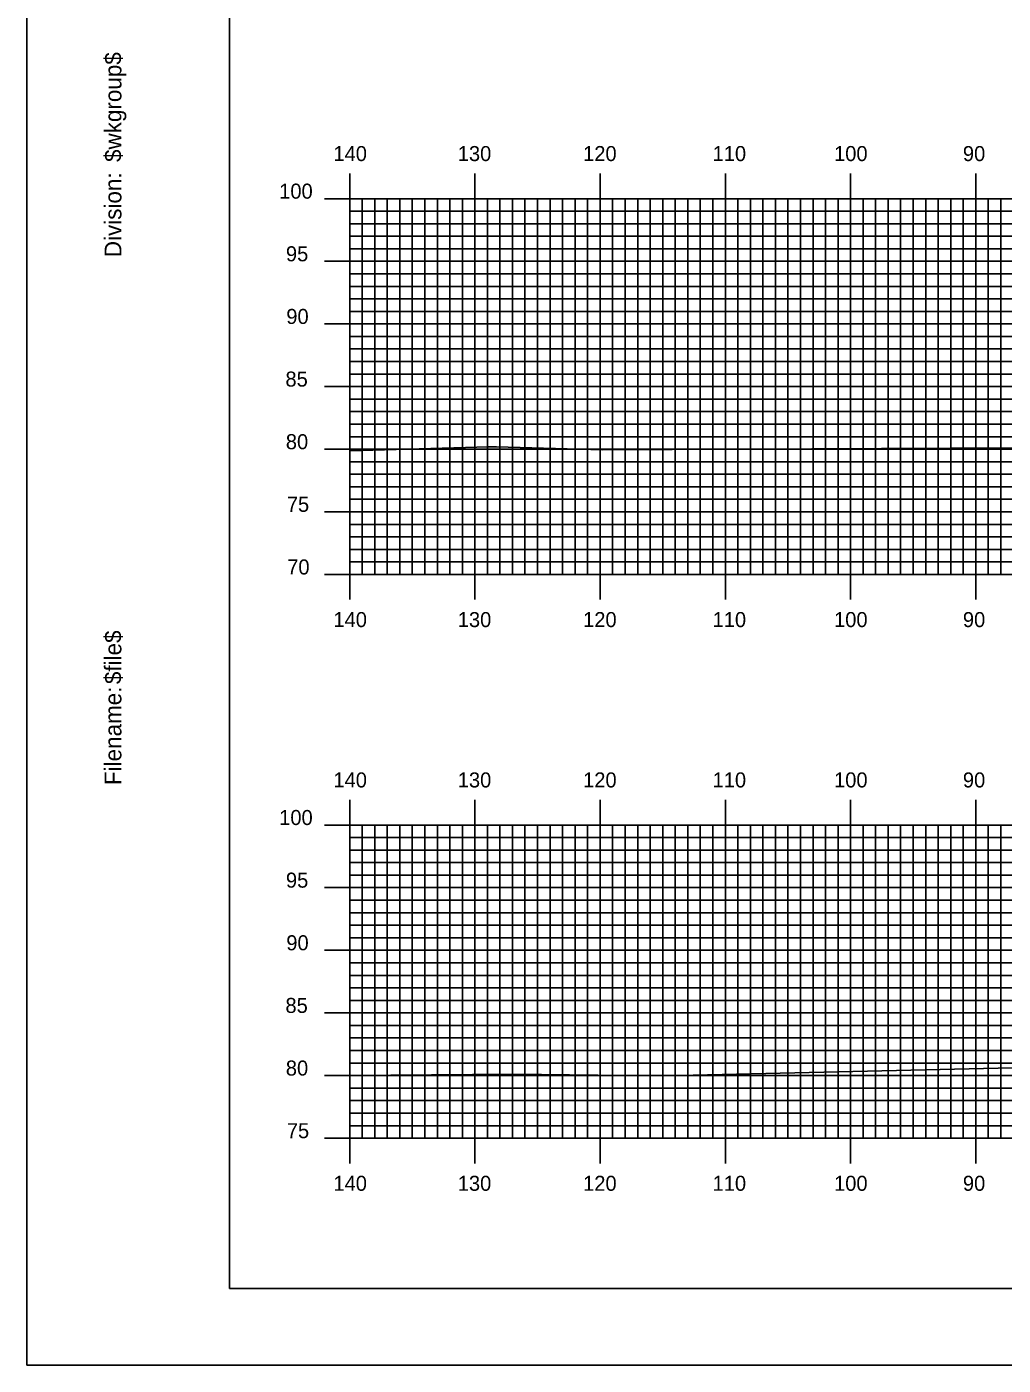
# Model space of a CAD drawing. Extents: x 1757462 to 1757806, y 442591 to 442811.
# Drawn here: x 1757462.3 to 1757540.3, y 442590.5 to 442697.4 of the extents above; entities that cross this region are included whole.
import ezdxf

# ---------------------------------------------------------------- set-up
doc = ezdxf.new("R2010")
doc.units = 0
for name, color, linetype in [('BORDER', 7, 'Continuous'), ('H_V ANNOTATION', 7, 'Continuous'), ('MAJOR', 7, 'Continuous'), ('MINOR', 7, 'Continuous'), ('PLOT BOUNDARY', 7, 'Continuous'), ('S_Roadway_Centerline', 7, 'Continuous')]:
    doc.layers.add(name, color=color, linetype=linetype)

msp = doc.modelspace()

# ---------------------------------------------------------------- linework, layer by layer
at = {"layer": 'BORDER'}
msp.add_lwpolyline([(1757478.51, 442596.67), (1757798.51, 442596.67), (1757798.51, 442806.67), (1757478.51, 442806.67)], close=True, dxfattribs=at)
at = {"layer": 'MAJOR'}
for p, q in [((1757488.11, 442685.67), (1757488.11, 442683.67)), ((1757498.11, 442685.67), (1757498.11, 442683.67)), ((1757508.11, 442685.67), (1757508.11, 442683.67)), ((1757518.11, 442685.67), (1757518.11, 442683.67)), ((1757528.11, 442685.67), (1757528.11, 442683.67)), ((1757538.11, 442685.67), (1757538.11, 442683.67)), ((1757486.11, 442683.67), (1757488.11, 442683.67)), ((1757488.11, 442683.67), (1757768.11, 442683.67)), ((1757488.11, 442653.67), (1757488.11, 442683.67)), ((1757488.11, 442653.67), (1757488.11, 442683.67)), ((1757488.11, 442683.67), (1757768.11, 442683.67)), ((1757498.11, 442653.67), (1757498.11, 442683.67)), ((1757508.11, 442653.67), (1757508.11, 442683.67)), ((1757518.11, 442653.67), (1757518.11, 442683.67)), ((1757528.11, 442653.67), (1757528.11, 442683.67)), ((1757538.11, 442653.67), (1757538.11, 442683.67)), ((1757486.11, 442678.67), (1757488.11, 442678.67)), ((1757488.11, 442678.67), (1757768.11, 442678.67)), ((1757486.11, 442673.67), (1757488.11, 442673.67)), ((1757488.11, 442673.67), (1757768.11, 442673.67)), ((1757486.11, 442668.67), (1757488.11, 442668.67)), ((1757488.11, 442668.67), (1757768.11, 442668.67)), ((1757486.11, 442663.67), (1757488.11, 442663.67)), ((1757488.11, 442663.67), (1757768.11, 442663.67)), ((1757486.11, 442658.67), (1757488.11, 442658.67)), ((1757488.11, 442658.67), (1757768.11, 442658.67)), ((1757486.11, 442653.67), (1757488.11, 442653.67)), ((1757488.11, 442653.67), (1757768.11, 442653.67)), ((1757488.11, 442653.67), (1757768.11, 442653.67)), ((1757488.11, 442651.66), (1757488.11, 442653.67)), ((1757498.11, 442651.66), (1757498.11, 442653.67)), ((1757508.11, 442651.66), (1757508.11, 442653.67)), ((1757518.11, 442651.66), (1757518.11, 442653.67)), ((1757528.11, 442651.66), (1757528.11, 442653.67)), ((1757538.11, 442651.66), (1757538.11, 442653.67)), ((1757488.11, 442635.67), (1757488.11, 442633.67)), ((1757498.11, 442635.67), (1757498.11, 442633.67)), ((1757508.11, 442635.67), (1757508.11, 442633.67)), ((1757518.11, 442635.67), (1757518.11, 442633.67)), ((1757528.11, 442635.67), (1757528.11, 442633.67)), ((1757538.11, 442635.67), (1757538.11, 442633.67)), ((1757486.11, 442633.67), (1757488.11, 442633.67)), ((1757488.11, 442633.67), (1757768.11, 442633.67)), ((1757488.11, 442608.67), (1757488.11, 442633.67)), ((1757488.11, 442608.67), (1757488.11, 442633.67)), ((1757488.11, 442633.67), (1757768.11, 442633.67)), ((1757498.11, 442608.67), (1757498.11, 442633.67)), ((1757508.11, 442608.67), (1757508.11, 442633.67)), ((1757518.11, 442608.67), (1757518.11, 442633.67)), ((1757528.11, 442608.67), (1757528.11, 442633.67)), ((1757538.11, 442608.67), (1757538.11, 442633.67)), ((1757486.11, 442628.67), (1757488.11, 442628.67)), ((1757488.11, 442628.67), (1757768.11, 442628.67)), ((1757486.11, 442623.67), (1757488.11, 442623.67)), ((1757488.11, 442623.67), (1757768.11, 442623.67)), ((1757486.11, 442618.67), (1757488.11, 442618.67)), ((1757488.11, 442618.67), (1757768.11, 442618.67)), ((1757486.11, 442613.67), (1757488.11, 442613.67)), ((1757488.11, 442613.67), (1757768.11, 442613.67)), ((1757486.11, 442608.67), (1757488.11, 442608.67)), ((1757488.11, 442608.67), (1757768.11, 442608.67)), ((1757488.11, 442608.67), (1757768.11, 442608.67)), ((1757488.11, 442606.66), (1757488.11, 442608.67)), ((1757498.11, 442606.66), (1757498.11, 442608.67)), ((1757508.11, 442606.66), (1757508.11, 442608.67)), ((1757518.11, 442606.66), (1757518.11, 442608.67)), ((1757528.11, 442606.66), (1757528.11, 442608.67)), ((1757538.11, 442606.66), (1757538.11, 442608.67))]:
    msp.add_line(p, q, dxfattribs=at)
at = {"layer": 'MINOR'}
for p, q in [((1757489.11, 442653.67), (1757489.11, 442683.67)), ((1757490.11, 442653.67), (1757490.11, 442683.67)), ((1757491.11, 442653.67), (1757491.11, 442683.67)), ((1757492.11, 442653.67), (1757492.11, 442683.67)), ((1757493.11, 442653.67), (1757493.11, 442683.67)), ((1757494.11, 442653.67), (1757494.11, 442683.67)), ((1757495.11, 442653.67), (1757495.11, 442683.67)), ((1757496.11, 442653.67), (1757496.11, 442683.67)), ((1757497.11, 442653.67), (1757497.11, 442683.67)), ((1757499.11, 442653.67), (1757499.11, 442683.67)), ((1757500.11, 442653.67), (1757500.11, 442683.67)), ((1757501.11, 442653.67), (1757501.11, 442683.67)), ((1757502.11, 442653.67), (1757502.11, 442683.67)), ((1757503.11, 442653.67), (1757503.11, 442683.67)), ((1757504.11, 442653.67), (1757504.11, 442683.67)), ((1757505.11, 442653.67), (1757505.11, 442683.67)), ((1757506.11, 442653.67), (1757506.11, 442683.67)), ((1757507.11, 442653.67), (1757507.11, 442683.67)), ((1757509.11, 442653.67), (1757509.11, 442683.67)), ((1757510.11, 442653.67), (1757510.11, 442683.67)), ((1757511.11, 442653.67), (1757511.11, 442683.67)), ((1757512.11, 442653.67), (1757512.11, 442683.67)), ((1757513.11, 442653.67), (1757513.11, 442683.67)), ((1757514.11, 442653.67), (1757514.11, 442683.67)), ((1757515.11, 442653.67), (1757515.11, 442683.67)), ((1757516.11, 442653.67), (1757516.11, 442683.67)), ((1757517.11, 442653.67), (1757517.11, 442683.67)), ((1757519.11, 442653.67), (1757519.11, 442683.67)), ((1757520.11, 442653.67), (1757520.11, 442683.67)), ((1757521.11, 442653.67), (1757521.11, 442683.67)), ((1757522.11, 442653.67), (1757522.11, 442683.67)), ((1757523.11, 442653.67), (1757523.11, 442683.67)), ((1757524.11, 442653.67), (1757524.11, 442683.67)), ((1757525.11, 442653.67), (1757525.11, 442683.67)), ((1757526.11, 442653.67), (1757526.11, 442683.67)), ((1757527.11, 442653.67), (1757527.11, 442683.67)), ((1757529.11, 442653.67), (1757529.11, 442683.67)), ((1757530.11, 442653.67), (1757530.11, 442683.67)), ((1757531.11, 442653.67), (1757531.11, 442683.67)), ((1757532.11, 442653.67), (1757532.11, 442683.67)), ((1757533.11, 442653.67), (1757533.11, 442683.67)), ((1757534.11, 442653.67), (1757534.11, 442683.67)), ((1757535.11, 442653.67), (1757535.11, 442683.67)), ((1757536.11, 442653.67), (1757536.11, 442683.67)), ((1757537.11, 442653.67), (1757537.11, 442683.67)), ((1757539.11, 442653.67), (1757539.11, 442683.67)), ((1757540.11, 442653.67), (1757540.11, 442683.67)), ((1757488.11, 442682.67), (1757768.11, 442682.67)), ((1757488.11, 442682.67), (1757490.11, 442682.67)), ((1757488.11, 442681.67), (1757768.11, 442681.67)), ((1757488.11, 442681.67), (1757490.11, 442681.67)), ((1757488.11, 442680.67), (1757768.11, 442680.67)), ((1757488.11, 442680.67), (1757490.11, 442680.67)), ((1757488.11, 442679.67), (1757768.11, 442679.67)), ((1757488.11, 442679.67), (1757490.11, 442679.67)), ((1757488.11, 442677.67), (1757768.11, 442677.67)), ((1757488.11, 442677.67), (1757490.11, 442677.67)), ((1757488.11, 442676.67), (1757768.11, 442676.67)), ((1757488.11, 442676.67), (1757490.11, 442676.67)), ((1757488.11, 442675.67), (1757768.11, 442675.67)), ((1757488.11, 442675.67), (1757490.11, 442675.67)), ((1757488.11, 442674.67), (1757768.11, 442674.67)), ((1757488.11, 442674.67), (1757490.11, 442674.67)), ((1757488.11, 442672.67), (1757768.11, 442672.67)), ((1757488.11, 442672.67), (1757490.11, 442672.67)), ((1757488.11, 442671.67), (1757768.11, 442671.67)), ((1757488.11, 442671.67), (1757490.11, 442671.67)), ((1757488.11, 442670.67), (1757768.11, 442670.67)), ((1757488.11, 442670.67), (1757490.11, 442670.67)), ((1757488.11, 442669.67), (1757768.11, 442669.67)), ((1757488.11, 442669.67), (1757490.11, 442669.67)), ((1757488.11, 442667.67), (1757768.11, 442667.67)), ((1757488.11, 442667.67), (1757490.11, 442667.67)), ((1757488.11, 442666.67), (1757768.11, 442666.67)), ((1757488.11, 442666.67), (1757490.11, 442666.67)), ((1757488.11, 442665.67), (1757768.11, 442665.67)), ((1757488.11, 442665.67), (1757490.11, 442665.67)), ((1757488.11, 442664.67), (1757768.11, 442664.67)), ((1757488.11, 442664.67), (1757490.11, 442664.67)), ((1757488.11, 442662.67), (1757768.11, 442662.67)), ((1757488.11, 442662.67), (1757490.11, 442662.67)), ((1757488.11, 442661.67), (1757768.11, 442661.67)), ((1757488.11, 442661.67), (1757490.11, 442661.67)), ((1757488.11, 442660.67), (1757768.11, 442660.67)), ((1757488.11, 442660.67), (1757490.11, 442660.67)), ((1757488.11, 442659.67), (1757768.11, 442659.67)), ((1757488.11, 442659.67), (1757490.11, 442659.67)), ((1757488.11, 442657.67), (1757768.11, 442657.67)), ((1757488.11, 442657.67), (1757490.11, 442657.67)), ((1757488.11, 442656.67), (1757768.11, 442656.67)), ((1757488.11, 442656.67), (1757490.11, 442656.67)), ((1757488.11, 442655.67), (1757768.11, 442655.67)), ((1757488.11, 442655.67), (1757490.11, 442655.67)), ((1757488.11, 442654.67), (1757768.11, 442654.67)), ((1757488.11, 442654.67), (1757490.11, 442654.67)), ((1757489.11, 442608.67), (1757489.11, 442633.67)), ((1757490.11, 442608.67), (1757490.11, 442633.67)), ((1757491.11, 442608.67), (1757491.11, 442633.67)), ((1757492.11, 442608.67), (1757492.11, 442633.67)), ((1757493.11, 442608.67), (1757493.11, 442633.67)), ((1757494.11, 442608.67), (1757494.11, 442633.67)), ((1757495.11, 442608.67), (1757495.11, 442633.67)), ((1757496.11, 442608.67), (1757496.11, 442633.67)), ((1757497.11, 442608.67), (1757497.11, 442633.67)), ((1757499.11, 442608.67), (1757499.11, 442633.67)), ((1757500.11, 442608.67), (1757500.11, 442633.67)), ((1757501.11, 442608.67), (1757501.11, 442633.67)), ((1757502.11, 442608.67), (1757502.11, 442633.67)), ((1757503.11, 442608.67), (1757503.11, 442633.67)), ((1757504.11, 442608.67), (1757504.11, 442633.67)), ((1757505.11, 442608.67), (1757505.11, 442633.67)), ((1757506.11, 442608.67), (1757506.11, 442633.67)), ((1757507.11, 442608.67), (1757507.11, 442633.67)), ((1757509.11, 442608.67), (1757509.11, 442633.67)), ((1757510.11, 442608.67), (1757510.11, 442633.67)), ((1757511.11, 442608.67), (1757511.11, 442633.67)), ((1757512.11, 442608.67), (1757512.11, 442633.67)), ((1757513.11, 442608.67), (1757513.11, 442633.67)), ((1757514.11, 442608.67), (1757514.11, 442633.67)), ((1757515.11, 442608.67), (1757515.11, 442633.67)), ((1757516.11, 442608.67), (1757516.11, 442633.67)), ((1757517.11, 442608.67), (1757517.11, 442633.67)), ((1757519.11, 442608.67), (1757519.11, 442633.67)), ((1757520.11, 442608.67), (1757520.11, 442633.67)), ((1757521.11, 442608.67), (1757521.11, 442633.67)), ((1757522.11, 442608.67), (1757522.11, 442633.67)), ((1757523.11, 442608.67), (1757523.11, 442633.67)), ((1757524.11, 442608.67), (1757524.11, 442633.67)), ((1757525.11, 442608.67), (1757525.11, 442633.67)), ((1757526.11, 442608.67), (1757526.11, 442633.67)), ((1757527.11, 442608.67), (1757527.11, 442633.67)), ((1757529.11, 442608.67), (1757529.11, 442633.67)), ((1757530.11, 442608.67), (1757530.11, 442633.67)), ((1757531.11, 442608.67), (1757531.11, 442633.67)), ((1757532.11, 442608.67), (1757532.11, 442633.67)), ((1757533.11, 442608.67), (1757533.11, 442633.67)), ((1757534.11, 442608.67), (1757534.11, 442633.67)), ((1757535.11, 442608.67), (1757535.11, 442633.67)), ((1757536.11, 442608.67), (1757536.11, 442633.67)), ((1757537.11, 442608.67), (1757537.11, 442633.67)), ((1757539.11, 442608.67), (1757539.11, 442633.67)), ((1757540.11, 442608.67), (1757540.11, 442633.67)), ((1757488.11, 442632.67), (1757768.11, 442632.67)), ((1757488.11, 442632.67), (1757490.11, 442632.67)), ((1757488.11, 442631.67), (1757768.11, 442631.67)), ((1757488.11, 442631.67), (1757490.11, 442631.67)), ((1757488.11, 442630.67), (1757768.11, 442630.67)), ((1757488.11, 442630.67), (1757490.11, 442630.67)), ((1757488.11, 442629.67), (1757768.11, 442629.67)), ((1757488.11, 442629.67), (1757490.11, 442629.67)), ((1757488.11, 442627.67), (1757768.11, 442627.67)), ((1757488.11, 442627.67), (1757490.11, 442627.67)), ((1757488.11, 442626.67), (1757768.11, 442626.67)), ((1757488.11, 442626.67), (1757490.11, 442626.67)), ((1757488.11, 442625.67), (1757768.11, 442625.67)), ((1757488.11, 442625.67), (1757490.11, 442625.67)), ((1757488.11, 442624.67), (1757768.11, 442624.67)), ((1757488.11, 442624.67), (1757490.11, 442624.67)), ((1757488.11, 442622.67), (1757768.11, 442622.67)), ((1757488.11, 442622.67), (1757490.11, 442622.67)), ((1757488.11, 442621.67), (1757768.11, 442621.67)), ((1757488.11, 442621.67), (1757490.11, 442621.67)), ((1757488.11, 442620.67), (1757768.11, 442620.67)), ((1757488.11, 442620.67), (1757490.11, 442620.67)), ((1757488.11, 442619.67), (1757768.11, 442619.67)), ((1757488.11, 442619.67), (1757490.11, 442619.67)), ((1757488.11, 442617.67), (1757768.11, 442617.67)), ((1757488.11, 442617.67), (1757490.11, 442617.67)), ((1757488.11, 442616.67), (1757768.11, 442616.67)), ((1757488.11, 442616.67), (1757490.11, 442616.67)), ((1757488.11, 442615.67), (1757768.11, 442615.67)), ((1757488.11, 442615.67), (1757490.11, 442615.67)), ((1757488.11, 442614.67), (1757768.11, 442614.67)), ((1757488.11, 442614.67), (1757490.11, 442614.67)), ((1757488.11, 442612.67), (1757768.11, 442612.67)), ((1757488.11, 442612.67), (1757490.11, 442612.67)), ((1757488.11, 442611.67), (1757768.11, 442611.67)), ((1757488.11, 442611.67), (1757490.11, 442611.67)), ((1757488.11, 442610.67), (1757768.11, 442610.67)), ((1757488.11, 442610.67), (1757490.11, 442610.67)), ((1757488.11, 442609.67), (1757768.11, 442609.67)), ((1757488.11, 442609.67), (1757490.11, 442609.67))]:
    msp.add_line(p, q, dxfattribs=at)
at = {"layer": 'PLOT BOUNDARY'}
msp.add_lwpolyline([(1757462.32, 442590.55), (1757802.32, 442590.55), (1757802.32, 442810.55), (1757462.32, 442810.55)], close=True, dxfattribs=at)
at = {"layer": 'S_Roadway_Centerline'}
for points in [[(1757488.11, 442663.53), (1757499.2, 442663.86), (1757499.48, 442663.86), (1757499.83, 442663.85), (1757508.3, 442663.61), (1757541.72, 442663.79), (1757560.06, 442664.28), (1757582.59, 442664.42), (1757590.13, 442664.45), (1757623.89, 442665.05), (1757628.78, 442665.07), (1757633.54, 442665.22), (1757663.8, 442665.29), (1757670.71, 442665.59), (1757685.16, 442665.37), (1757688.21, 442665.32), (1757699.07, 442665.67)], [(1757488.11, 442613.68), (1757501.17, 442613.77), (1757507.94, 442613.71), (1757514.36, 442613.67), (1757553.81, 442614.57), (1757553.88, 442614.57), (1757554, 442614.57), (1757581.3, 442614.24), (1757598.31, 442614.07), (1757601.32, 442614.11), (1757627.79, 442614.8), (1757645.88, 442614.86), (1757665.07, 442614.91), (1757687.39, 442614.71), (1757688.63, 442614.72), (1757691.05, 442614.71), (1757726.03, 442615.16), (1757736.49, 442615.21), (1757747, 442615.3), (1757756.19, 442615.67), (1757758.95, 442615.74), (1757767.31, 442615.61), (1757768.11, 442615.6)]]:
    msp.add_lwpolyline(points, dxfattribs=at)

# ---------------------------------------------------------------- texts
at = {"layer": 'BORDER'}
for s, p in [('$wkgroup$', (1757469.88, 442686.6)), ('$wkgroup$', (1757469.88, 442686.6)), ('Division:', (1757469.88, 442679)), ('Division:', (1757469.88, 442679)), ('$file$', (1757469.88, 442644.92)), ('$file$', (1757469.88, 442644.92)), ('Filename:', (1757469.88, 442636.86)), ('Filename:', (1757469.88, 442636.86))]:
    msp.add_text(s, height=1.339, rotation=90, dxfattribs=at).set_placement(p)
at = {"layer": 'H_V ANNOTATION'}
for s, p in [('140', (1757486.81, 442686.67)), ('130', (1757496.74, 442686.67)), ('120', (1757506.75, 442686.67)), ('110', (1757517.09, 442686.67)), ('100', (1757526.79, 442686.67)), ('90', (1757537.08, 442686.67)), ('100', (1757482.48, 442683.67)), ('95', (1757483.02, 442678.67)), ('90', (1757483.05, 442673.67)), ('85', (1757482.98, 442668.67)), ('80', (1757483.01, 442663.67)), ('75', (1757483.09, 442658.67)), ('70', (1757483.12, 442653.67)), ('140', (1757486.81, 442649.47)), ('130', (1757496.74, 442649.47)), ('120', (1757506.75, 442649.47)), ('110', (1757517.09, 442649.47)), ('100', (1757526.79, 442649.47)), ('90', (1757537.08, 442649.47)), ('140', (1757486.81, 442636.67)), ('130', (1757496.74, 442636.67)), ('120', (1757506.75, 442636.67)), ('110', (1757517.09, 442636.67)), ('100', (1757526.79, 442636.67)), ('90', (1757537.08, 442636.67)), ('100', (1757482.48, 442633.67)), ('95', (1757483.02, 442628.67)), ('90', (1757483.05, 442623.67)), ('85', (1757482.98, 442618.67)), ('80', (1757483.01, 442613.67)), ('75', (1757483.09, 442608.67)), ('140', (1757486.81, 442604.47)), ('130', (1757496.74, 442604.47)), ('120', (1757506.75, 442604.47)), ('110', (1757517.09, 442604.47)), ('100', (1757526.79, 442604.47)), ('90', (1757537.08, 442604.47))]:
    msp.add_text(s, height=1.2, dxfattribs=at).set_placement(p)
at = {"layer": 'MAJOR'}
for p in [(1757488.1, 442653.67), (1757488.1, 442608.67)]:
    msp.add_text('-', height=0.012, dxfattribs=at).set_placement(p)

doc.saveas('drawing.dxf')
